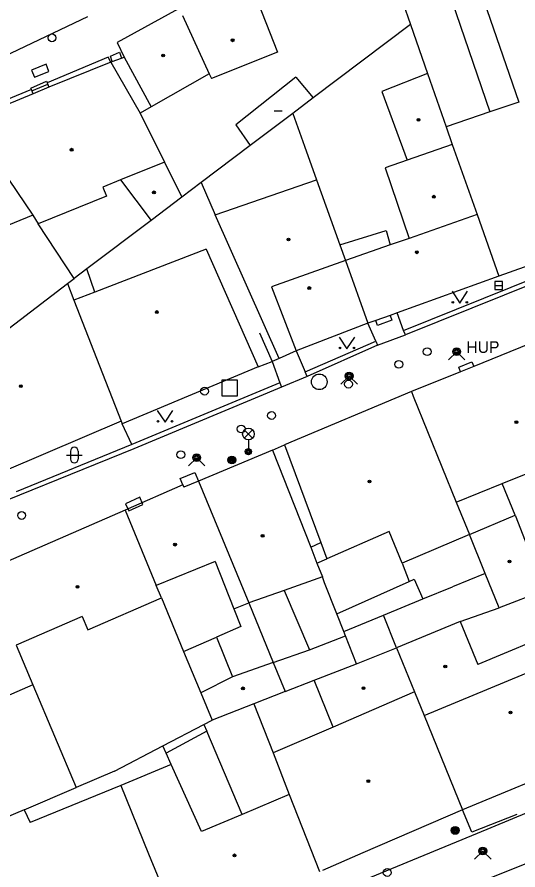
# Model space of a CAD drawing. Extents: x -598233 to -596890, y -1157848 to -1156431.
# Drawn here: x -597251.6 to -597219.5, y -1157487.3 to -1157432.7 of the extents above; entities that cross this region are included whole.
import ezdxf

# ---------------------------------------------------------------- set-up
doc = ezdxf.new("R2010")
doc.units = 0
for name, color, linetype in [('Level 10', 7, 'Continuous'), ('Level 11', 7, 'Continuous'), ('Level 24', 7, 'Continuous'), ('Level 25', 7, 'Continuous'), ('Level 26', 7, 'Continuous'), ('Level 27', 7, 'Continuous'), ('Level 28', 7, 'Continuous'), ('Level 31', 7, 'Continuous'), ('Level 33', 7, 'Continuous'), ('Level 36', 7, 'Continuous'), ('Level 39', 7, 'Continuous'), ('Level 41', 7, 'Continuous'), ('Level 5', 7, 'Continuous'), ('Level 7', 7, 'Continuous'), ('Level 8', 7, 'Continuous')]:
    doc.layers.add(name, color=color, linetype=linetype)

msp = doc.modelspace()

# ---------------------------------------------------------------- linework, layer by layer
at = {"layer": 'Level 10'}
for points in [[(-597213.31, -1157481.35), (-597222.11, -1157485), (-597231.38, -1157488.83)], [(-597212.1, -1157484.2), (-597221.2, -1157487.83), (-597226.08, -1157489.78), (-597230.5, -1157491.55), (-597231.34, -1157491.88)]]:
    msp.add_lwpolyline(points, dxfattribs=at)
at = {"layer": 'Level 11'}
for points in [[(-597227.36, -1157430.34), (-597226.38, -1157433.18)], [(-597226.38, -1157433.18), (-597232.61, -1157437.88)], [(-597226.38, -1157433.18), (-597225.29, -1157436.32)], [(-597245.48, -1157435.55), (-597245.6, -1157435.2), (-597245.02, -1157434.94), (-597244.88, -1157435.33)], [(-597245.57, -1157435.58), (-597245.75, -1157435.27), (-597249.64, -1157436.92)], [(-597245.57, -1157435.58), (-597245.48, -1157435.55)], [(-597245.48, -1157435.55), (-597244.88, -1157435.33)], [(-597244.88, -1157435.33), (-597244.7199, -1157435.27)], [(-597250.6599, -1157437.34), (-597250.7, -1157437.25), (-597249.69, -1157436.81), (-597249.64, -1157436.92)], [(-597250.6599, -1157437.34), (-597254.86, -1157439.07), (-597254.69, -1157439.32)], [(-597250.54, -1157437.62), (-597250.6599, -1157437.34)], [(-597250.62, -1157437.43), (-597249.61, -1157437.01)], [(-597249.64, -1157436.92), (-597249.53, -1157437.2)], [(-597242.99, -1157438.45), (-597243.69, -1157438.85)], [(-597233.9099, -1157438.87), (-597233.1599, -1157440.9699), (-597232.4, -1157443.12)], [(-597236.64, -1157440.93), (-597239.79, -1157443.31)], [(-597239.79, -1157443.31), (-597241.02, -1157444.24)], [(-597247.92, -1157449.46), (-597250.2199, -1157445.94)], [(-597242.99, -1157445.73), (-597247.1, -1157448.84)], [(-597230.9099, -1157447.29), (-597227.94, -1157446.38), (-597227.69, -1157447.3)], [(-597247.1, -1157448.84), (-597247.92, -1157449.46)], [(-597246.59, -1157450.32), (-597247.1, -1157448.84)], [(-597248.34, -1157449.78), (-597247.92, -1157449.46)], [(-597227.68, -1157451.81), (-597227.57, -1157452.12), (-597228.5, -1157452.46), (-597228.61, -1157452.14)], [(-597226.83, -1157452.78), (-597227.24, -1157451.65)], [(-597228.61, -1157453.46), (-597229.11, -1157452.32)], [(-597236.04, -1157452.93), (-597235.23, -1157454.76)], [(-597233.71, -1157454.09), (-597233.12, -1157455.43)], [(-597235.23, -1157454.76), (-597234.74, -1157456.14)], [(-597223.17, -1157455.43), (-597223.28, -1157455.13), (-597222.45, -1157454.79), (-597222.33, -1157455.08)], [(-597232.99, -1157455.7199), (-597234.64, -1157456.42)], [(-597244.2199, -1157460.09), (-597244.84, -1157458.77)], [(-597235.21, -1157460.44), (-597234.45, -1157460.1)], [(-597240.96, -1157462.6599), (-597241.13, -1157462.26), (-597240.2, -1157461.87), (-597239.96, -1157462.43)], [(-597219.67, -1157464.62), (-597220.5, -1157462.59)], [(-597232.77, -1157466.6599), (-597232.12, -1157466.36)], [(-597232.37, -1157467.69), (-597231.73, -1157467.4099)], [(-597226.92, -1157467.68), (-597226.47, -1157468.87)], [(-597231.09, -1157470.94), (-597231.88, -1157468.94), (-597232.02, -1157468.56)], [(-597221.6, -1157468.35), (-597223.7, -1157469.21)], [(-597231.09, -1157470.94), (-597226.47, -1157468.87), (-597226.14, -1157468.72)], [(-597226.14, -1157468.7199), (-597225.6, -1157469.98)], [(-597234.46, -1157469.43), (-597232.85, -1157473.24)], [(-597225.6, -1157469.98), (-597223.7, -1157469.21)], [(-597242.33, -1157469.9099), (-597240.9099, -1157473.34)], [(-597230.65, -1157472.06), (-597228.11, -1157471.01), (-597225.6, -1157469.98)], [(-597237.69, -1157470.62), (-597237.24, -1157471.75), (-597238.81, -1157472.43)], [(-597236.74, -1157470.24), (-597235.17, -1157474.05)], [(-597223.2, -1157471.43), (-597220.71, -1157470.56)], [(-597230.65, -1157472.06), (-597231.09, -1157470.94)], [(-597227.27, -1157473.12), (-597228.11, -1157471.01)], [(-597232.85, -1157473.24), (-597230.54, -1157472.35)], [(-597230.54, -1157472.35), (-597230.65, -1157472.06)], [(-597229.84, -1157474.13), (-597230.54, -1157472.35)], [(-597240.9099, -1157473.34), (-597238.81, -1157472.43)], [(-597238.81, -1157472.43), (-597237.77, -1157474.96)], [(-597240.9099, -1157473.34), (-597239.81, -1157476)], [(-597235.17, -1157474.05), (-597232.85, -1157473.24)], [(-597250.57, -1157475.49), (-597247.79, -1157482.07)], [(-597234.4, -1157475.9099), (-597232.55, -1157475.19)], [(-597236.42, -1157476.7), (-597235.18, -1157479.85)], [(-597239.62, -1157478.02), (-597239.09, -1157477.74)], [(-597242.24, -1157479.4), (-597239.62, -1157478.02)], [(-597239.62, -1157478.02), (-597239.43, -1157478.46)], [(-597239.43, -1157478.46), (-597242.03, -1157479.86)], [(-597237.1599, -1157483.78), (-597239.43, -1157478.46)], [(-597245.33, -1157481.02), (-597242.24, -1157479.4)], [(-597242.03, -1157479.86), (-597242.24, -1157479.4)], [(-597241.7, -1157480.59), (-597242.03, -1157479.86)], [(-597245.33, -1157481.02), (-597247.79, -1157482.07)], [(-597251.13, -1157483.49), (-597247.79, -1157482.07)], [(-597219.57, -1157483.79), (-597222.45, -1157484.93), (-597223.04, -1157483.49)]]:
    msp.add_lwpolyline(points, dxfattribs=at)
at = {"layer": 'Level 24'}
for points in [[(-597250.4593, -1157436.5597), (-597249.5327, -1157436.1836), (-597249.7207, -1157435.7203), (-597250.6473, -1157436.0964)], [(-597244.4237, -1157464.3329), (-597243.5115, -1157463.9233), (-597243.7163, -1157463.4671), (-597244.6285, -1157463.8767)]]:
    msp.add_lwpolyline(points, close=True, dxfattribs=at)
at = {"layer": 'Level 25'}
for centre, radius in [((-597237.82, -1157461.08), 0.25), ((-597237.82, -1157461.08), 0.2), ((-597237.82, -1157461.08), 0.15), ((-597237.82, -1157461.08), 0.1), ((-597237.82, -1157461.08), 0.05), ((-597223.52, -1157484.81), 0.25), ((-597223.52, -1157484.81), 0.2), ((-597223.52, -1157484.81), 0.15), ((-597223.52, -1157484.81), 0.1), ((-597223.52, -1157484.81), 0.05)]:
    msp.add_circle(centre, radius, dxfattribs=at)
at = {"layer": 'Level 26'}
msp.add_lwpolyline([(-597238.46, -1157456.96), (-597237.46, -1157456.96), (-597237.46, -1157455.96), (-597238.46, -1157455.96)], close=True, dxfattribs=at)
at = {"layer": 'Level 27'}
msp.add_line((-597220.99, -1157449.9), (-597220.49, -1157449.9), dxfattribs=at)
msp.add_lwpolyline([(-597220.99, -1157450.15), (-597220.49, -1157450.15), (-597220.49, -1157449.65), (-597220.99, -1157449.65)], close=True, dxfattribs=at)
msp.add_circle((-597232.2199, -1157456.07), 0.5, dxfattribs=at)
at = {"layer": 'Level 28'}
for centre in [(-597249.34, -1157434.03), (-597225.31, -1157454.14), (-597227.13, -1157454.95), (-597230.35, -1157456.2199), (-597239.57, -1157456.67), (-597235.28, -1157458.23), (-597237.2199, -1157459.09), (-597241.09, -1157460.74), (-597251.28, -1157464.63), (-597227.87, -1157487.51)]:
    msp.add_circle(centre, 0.25, dxfattribs=at)
at = {"layer": 'Level 31'}
for points in [[(-597223.95, -1157454.67), (-597223.42, -1157454.14), (-597222.89, -1157454.67)], [(-597230.84, -1157456.23), (-597230.31, -1157455.7), (-597229.78, -1157456.23)], [(-597240.6, -1157461.46), (-597240.07, -1157460.93), (-597239.54, -1157461.46)], [(-597222.28, -1157486.66), (-597221.75, -1157486.13), (-597221.22, -1157486.66)]]:
    msp.add_lwpolyline(points, dxfattribs=at)
for centre, radius in [((-597223.42, -1157454.14), 0.25), ((-597223.42, -1157454.14), 0.18), ((-597223.42, -1157454.14), 0.11), ((-597230.31, -1157455.7), 0.25), ((-597230.31, -1157455.7), 0.18), ((-597230.31, -1157455.7), 0.11), ((-597240.07, -1157460.93), 0.25), ((-597240.07, -1157460.93), 0.18), ((-597240.07, -1157460.93), 0.11), ((-597221.75, -1157486.13), 0.25), ((-597221.75, -1157486.13), 0.18), ((-597221.75, -1157486.13), 0.11)]:
    msp.add_circle(centre, radius, dxfattribs=at)
at = {"layer": 'Level 33'}
for p, q in [((-597237.025, -1157459.68), (-597236.495, -1157459.15)), ((-597237.025, -1157459.15), (-597236.495, -1157459.68)), ((-597236.76, -1157459.79), (-597236.76, -1157460.54))]:
    msp.add_line(p, q, dxfattribs=at)
for centre, radius in [((-597236.76, -1157459.415), 0.375), ((-597236.76, -1157460.54), 0.2), ((-597236.76, -1157460.54), 0.1445), ((-597236.76, -1157460.54), 0.0876)]:
    msp.add_circle(centre, radius, dxfattribs=at)
at = {"layer": 'Level 36'}
for p, q in [((-597248.406, -1157460.766), (-597247.406, -1157460.766)), ((-597248.156, -1157460.516), (-597248.156, -1157461.016)), ((-597247.656, -1157460.516), (-597247.656, -1157461.016))]:
    msp.add_line(p, q, dxfattribs=at)
for points in [[(-597223.7199, -1157450.27), (-597223.2199, -1157451.02), (-597222.7199, -1157450.27)], [(-597230.95, -1157453.2), (-597230.45, -1157453.95), (-597229.95, -1157453.2)], [(-597242.6, -1157457.9), (-597242.1, -1157458.65), (-597241.6, -1157457.9)]]:
    msp.add_lwpolyline(points, dxfattribs=at)
for centre in [(-597223.6701, -1157450.9698), (-597222.7707, -1157450.9698), (-597230.9002, -1157453.8998), (-597230.0008, -1157453.8998), (-597242.5502, -1157458.5998), (-597241.6508, -1157458.5998)]:
    msp.add_circle(centre, 0.05, dxfattribs=at)
for centre, start, end in [((-597247.9057, -1157460.5163), 0, 180), ((-597247.9057, -1157461.0163), 180, 0)]:
    msp.add_arc(centre, 0.25, start, end, dxfattribs=at)
at = {"layer": 'Level 39'}
msp.add_line((-597235.1, -1157438.71), (-597234.6, -1157438.71), dxfattribs=at)
for centre, radius in [((-597237.77, -1157434.19), 0.09), ((-597237.77, -1157434.19), 0.0398), ((-597242.2199, -1157435.1599), 0.09), ((-597242.2199, -1157435.1599), 0.0398), ((-597225.87, -1157439.28), 0.09), ((-597225.87, -1157439.28), 0.0398), ((-597248.08, -1157441.2), 0.09), ((-597248.08, -1157441.2), 0.0398), ((-597242.81, -1157443.93), 0.09), ((-597242.81, -1157443.93), 0.0398), ((-597224.88, -1157444.21), 0.09), ((-597224.88, -1157444.21), 0.0398), ((-597234.19, -1157446.95), 0.09), ((-597234.19, -1157446.95), 0.0398), ((-597225.9699, -1157447.77), 0.09), ((-597225.9699, -1157447.77), 0.0398), ((-597232.86, -1157450.06), 0.09), ((-597232.86, -1157450.06), 0.0398), ((-597242.63, -1157451.6), 0.09), ((-597242.63, -1157451.6), 0.0398), ((-597251.33, -1157456.35), 0.09), ((-597251.33, -1157456.35), 0.0398), ((-597219.6, -1157458.65), 0.09), ((-597219.6, -1157458.65), 0.0398), ((-597229, -1157462.46), 0.09), ((-597229, -1157462.46), 0.0398), ((-597235.85, -1157465.94), 0.09), ((-597235.85, -1157465.94), 0.0398), ((-597241.46, -1157466.5), 0.09), ((-597241.46, -1157466.5), 0.0398), ((-597220.04, -1157467.58), 0.09), ((-597220.04, -1157467.58), 0.0398), ((-597247.7, -1157469.21), 0.09), ((-597247.7, -1157469.21), 0.0398), ((-597224.15, -1157474.31), 0.09), ((-597224.15, -1157474.31), 0.0398), ((-597237.11, -1157475.71), 0.09), ((-597237.11, -1157475.71), 0.0398), ((-597229.39, -1157475.7), 0.09), ((-597229.39, -1157475.7), 0.0398), ((-597219.98, -1157477.26), 0.09), ((-597219.98, -1157477.26), 0.0398), ((-597229.08, -1157481.65), 0.09), ((-597229.08, -1157481.65), 0.0398), ((-597237.65, -1157486.4099), 0.09), ((-597237.65, -1157486.4099), 0.0398)]:
    msp.add_circle(centre, radius, dxfattribs=at)
at = {"layer": 'Level 5'}
for points in [[(-597223.32, -1157426.88), (-597221.9, -1157431.03), (-597219.45, -1157438.16)], [(-597236.4, -1157431.13), (-597234.9, -1157434.94)], [(-597223.73, -1157431.6599), (-597221.29, -1157438.78)], [(-597241.23, -1157432.17), (-597245.1599, -1157434.32)], [(-597240.99, -1157432.61), (-597239.27, -1157436.33)], [(-597245.1599, -1157434.32), (-597244.7199, -1157435.27)], [(-597234.9, -1157434.94), (-597239.13, -1157436.63)], [(-597245.57, -1157435.58), (-597249.53, -1157437.2)], [(-597245.57, -1157435.58), (-597243.69, -1157438.85)], [(-597244.7199, -1157435.27), (-597242.99, -1157438.45)], [(-597239.27, -1157436.33), (-597242.99, -1157438.45)], [(-597239.27, -1157436.33), (-597239.13, -1157436.63)], [(-597225.29, -1157436.32), (-597228.2199, -1157437.46)], [(-597225.29, -1157436.32), (-597224.1, -1157439.74)], [(-597233.7199, -1157436.55), (-597237.56, -1157439.61)], [(-597233.7199, -1157436.55), (-597232.61, -1157437.88)], [(-597249.53, -1157437.2), (-597250.54, -1157437.62)], [(-597250.54, -1157437.62), (-597254.69, -1157439.32)], [(-597232.61, -1157437.88), (-597233.9099, -1157438.87)], [(-597228.2199, -1157437.46), (-597226.59, -1157441.86)], [(-597219.45, -1157438.1599), (-597221.29, -1157438.78)], [(-597243.69, -1157438.85), (-597242.14, -1157441.99)], [(-597233.9099, -1157438.87), (-597236.64, -1157440.93)], [(-597221.29, -1157438.78), (-597224.1, -1157439.74)], [(-597254.69, -1157439.32), (-597250.57, -1157445.4)], [(-597237.56, -1157439.61), (-597236.64, -1157440.93)], [(-597224.1, -1157439.74), (-597223.71, -1157440.87)], [(-597223.71, -1157440.87), (-597226.59, -1157441.86)], [(-597223.71, -1157440.87), (-597222.11, -1157445.36)], [(-597242.14, -1157441.99), (-597244.96, -1157443.13)], [(-597242.14, -1157441.99), (-597241.02, -1157444.24)], [(-597226.59, -1157441.86), (-597228.01, -1157442.35)], [(-597228.01, -1157442.35), (-597226.4699, -1157446.88)], [(-597244.96, -1157443.13), (-597246.09, -1157443.59)], [(-597244.96, -1157443.13), (-597242.99, -1157445.73)], [(-597238.88, -1157445.38), (-597232.4, -1157443.12)], [(-597232.4, -1157443.12), (-597230.9099, -1157447.29)], [(-597246.09, -1157443.59), (-597245.84, -1157444.17)], [(-597245.84, -1157444.17), (-597250.2199, -1157445.94)], [(-597241.02, -1157444.24), (-597242.99, -1157445.73)], [(-597250.57, -1157445.4), (-597256.3, -1157447.74)], [(-597250.57, -1157445.4), (-597250.2199, -1157445.94)], [(-597234.8, -1157454.57), (-597238.88, -1157445.38)], [(-597222.11, -1157445.36), (-597226.4699, -1157446.88)], [(-597222.11, -1157445.36), (-597220.73, -1157449.31)], [(-597226.4699, -1157446.88), (-597227.69, -1157447.3)], [(-597239.46, -1157447.57), (-597246.59, -1157450.32)], [(-597239.46, -1157447.57), (-597236.14, -1157455.11)], [(-597230.9099, -1157447.29), (-597230.54, -1157448.3)], [(-597227.69, -1157447.3), (-597230.54, -1157448.3)], [(-597230.54, -1157448.3), (-597235.29, -1157449.98)], [(-597230.54, -1157448.3), (-597229.11, -1157452.32)], [(-597216.82, -1157447.92), (-597220.73, -1157449.31)], [(-597220.73, -1157449.31), (-597227.24, -1157451.65)], [(-597252.75, -1157453.12), (-597248.34, -1157449.78)], [(-597248.34, -1157449.78), (-597247.93, -1157450.83)], [(-597235.29, -1157449.98), (-597233.71, -1157454.09)], [(-597246.59, -1157450.32), (-597247.93, -1157450.83)], [(-597247.93, -1157450.83), (-597246.48, -1157454.55)], [(-597228.61, -1157452.14), (-597229.11, -1157452.32)], [(-597227.68, -1157451.81), (-597228.61, -1157452.14)], [(-597227.24, -1157451.65), (-597227.68, -1157451.81)], [(-597229.11, -1157452.32), (-597233.71, -1157454.09)], [(-597217.03, -1157452.94), (-597222.33, -1157455.08)], [(-597233.71, -1157454.09), (-597234.8, -1157454.57)], [(-597246.48, -1157454.55), (-597244.9, -1157458.6)], [(-597236.14, -1157455.11), (-597244.84, -1157458.77)], [(-597223.17, -1157455.43), (-597226.32, -1157456.7)], [(-597222.33, -1157455.08), (-597223.17, -1157455.43)], [(-597226.32, -1157456.7), (-597234.45, -1157460.1)], [(-597226.32, -1157456.7), (-597226.21, -1157456.98)], [(-597226.21, -1157456.98), (-597223.45, -1157463.78)], [(-597244.9, -1157458.6), (-597252.25, -1157461.73)], [(-597244.9, -1157458.6), (-597244.84, -1157458.77)], [(-597234.45, -1157460.1), (-597232.12, -1157466.36)], [(-597223.45, -1157463.78), (-597220.5, -1157462.59), (-597214.25, -1157460.07)], [(-597235.21, -1157460.44), (-597239.96, -1157462.43)], [(-597235.21, -1157460.44), (-597232.77, -1157466.6599)], [(-597239.96, -1157462.43), (-597240.89, -1157462.82)], [(-597239.96, -1157462.43), (-597236.74, -1157470.24)], [(-597240.96, -1157462.6599), (-597244.65, -1157464.29)], [(-597240.96, -1157462.6599), (-597240.89, -1157462.82)], [(-597223.45, -1157463.78), (-597222.61, -1157465.86)], [(-597244.65, -1157464.29), (-597253.64, -1157468.21)], [(-597244.65, -1157464.29), (-597242.6599, -1157469.11)], [(-597222.61, -1157465.86), (-597219.67, -1157464.62)], [(-597219.67, -1157464.62), (-597218.74, -1157467.03)], [(-597227.74, -1157465.6599), (-597231.73, -1157467.4099)], [(-597226.92, -1157467.68), (-597227.74, -1157465.6599)], [(-597232.12, -1157466.36), (-597231.73, -1157467.4099)], [(-597222.61, -1157465.86), (-597226.92, -1157467.68)], [(-597221.6, -1157468.35), (-597222.61, -1157465.86)], [(-597232.77, -1157466.6599), (-597232.37, -1157467.69)], [(-597238.89, -1157467.59), (-597242.6599, -1157469.11)], [(-597238.89, -1157467.59), (-597237.69, -1157470.62)], [(-597232.37, -1157467.69), (-597232.02, -1157468.56)], [(-597232.02, -1157468.56), (-597234.46, -1157469.43)], [(-597220.71, -1157470.56), (-597221.6, -1157468.35)], [(-597242.33, -1157469.9099), (-597242.6599, -1157469.11)], [(-597234.46, -1157469.43), (-597236.74, -1157470.24)], [(-597217.82, -1157469.43), (-597220.71, -1157470.56)], [(-597247.04, -1157471.96), (-597242.33, -1157469.9099)], [(-597237.69, -1157470.62), (-597236.74, -1157470.24)], [(-597247.4, -1157471.11), (-597251.64, -1157472.95)], [(-597247.4, -1157471.11), (-597247.04, -1157471.96)], [(-597223.2, -1157471.43), (-597227.27, -1157473.12)], [(-597223.2, -1157471.43), (-597222.06, -1157474.17)], [(-597216.75, -1157471.96), (-597222.06, -1157474.17)], [(-597251.64, -1157472.95), (-597250.57, -1157475.49)], [(-597229.84, -1157474.13), (-597227.27, -1157473.12)], [(-597227.27, -1157473.12), (-597226.12, -1157475.94)], [(-597225.5, -1157477.45), (-597216.09, -1157473.54)], [(-597235.17, -1157474.05), (-597237.77, -1157474.96)], [(-597235.17, -1157474.05), (-597234.4, -1157475.9099)], [(-597232.55, -1157475.19), (-597229.84, -1157474.13)], [(-597237.77, -1157474.96), (-597239.81, -1157476)], [(-597250.57, -1157475.49), (-597259.61, -1157479.43)], [(-597231.33, -1157478.19), (-597232.55, -1157475.19)], [(-597239.81, -1157476), (-597239.09, -1157477.74)], [(-597234.4, -1157475.9099), (-597236.42, -1157476.7)], [(-597226.12, -1157475.94), (-597231.33, -1157478.19)], [(-597226.12, -1157475.94), (-597225.5, -1157477.45)], [(-597236.42, -1157476.7), (-597239.09, -1157477.74)], [(-597225.5, -1157477.45), (-597223.04, -1157483.49)], [(-597231.33, -1157478.19), (-597235.18, -1157479.85)], [(-597235.18, -1157479.85), (-597234.14, -1157482.51)], [(-597241.7, -1157480.59), (-597244.92, -1157481.94)], [(-597239.77, -1157484.88), (-597241.7, -1157480.59)], [(-597215.73, -1157480.46), (-597223.04, -1157483.49)], [(-597244.92, -1157481.94), (-597250.73, -1157484.31)], [(-597244.92, -1157481.94), (-597243.15, -1157486.3)], [(-597234.14, -1157482.51), (-597237.1599, -1157483.78)], [(-597234.14, -1157482.51), (-597232.2, -1157487.45)], [(-597251.13, -1157483.49), (-597254.51, -1157484.92)], [(-597251.13, -1157483.49), (-597250.73, -1157484.31)], [(-597237.1599, -1157483.78), (-597239.77, -1157484.88)], [(-597223.04, -1157483.49), (-597229.43, -1157486.25)], [(-597243.15, -1157486.3), (-597241.09, -1157491.32)], [(-597229.43, -1157486.25), (-597232.02, -1157487.37)]]:
    msp.add_lwpolyline(points, dxfattribs=at)
at = {"layer": 'Level 7'}
for points in [[(-597247.06, -1157432.68), (-597252.88, -1157435.44)], [(-597239.79, -1157443.31), (-597238.88, -1157445.38)], [(-597226.83, -1157452.78), (-597216.53, -1157448.64), (-597216.82, -1157447.92)], [(-597216.14, -1157448.81), (-597226.71, -1157453.05)], [(-597226.71, -1157453.05), (-597226.83, -1157452.78)], [(-597233.12, -1157455.43), (-597228.61, -1157453.46)], [(-597228.49, -1157453.73), (-597232.99, -1157455.7199)], [(-597228.61, -1157453.46), (-597228.49, -1157453.73)], [(-597234.8, -1157454.57), (-597235.23, -1157454.76)], [(-597232.99, -1157455.7199), (-597233.12, -1157455.43)], [(-597234.74, -1157456.14), (-597244.2199, -1157460.09)], [(-597234.64, -1157456.42), (-597244.09, -1157460.36)], [(-597234.74, -1157456.14), (-597234.64, -1157456.42)], [(-597244.09, -1157460.36), (-597255.49, -1157464.9699)], [(-597244.2199, -1157460.09), (-597251.63, -1157463.11)]]:
    msp.add_lwpolyline(points, dxfattribs=at)
at = {"layer": 'Level 8'}
for points in [[(-597228.49, -1157453.73), (-597226.71, -1157453.05)], [(-597236.14, -1157455.11), (-597235.23, -1157454.76)]]:
    msp.add_lwpolyline(points, dxfattribs=at)

# ---------------------------------------------------------------- texts
at = {"layer": 'Level 41'}
msp.add_text('HUP', height=0.75, dxfattribs=at).set_placement((-597222.8, -1157454.2199))

doc.saveas('drawing.dxf')
